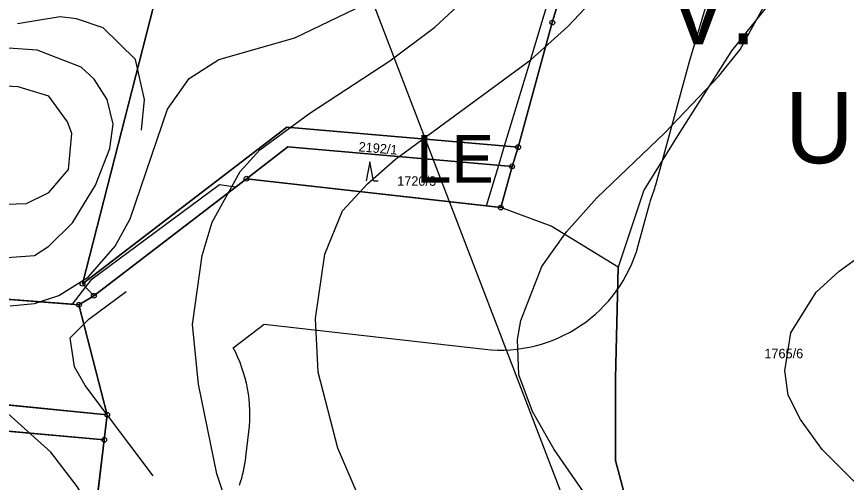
# Model space of a CAD drawing. Extents: x -706130 to -698555, y -971544 to -967260.
# Drawn here: x -703788.9 to -703614.4, y -970856.1 to -970758.1 of the extents above; entities that cross this region are included whole.
import ezdxf

# ---------------------------------------------------------------- set-up
doc = ezdxf.new("R2010")
doc.units = 0
for name, color, linetype in [('Archeologická naleziště S', 7, 'Continuous'), ('BPEJ hranice S', 7, 'Continuous'), ('BPEJ kód', 7, 'Continuous'), ('KN_Hranice_parcel', 7, 'Continuous'), ('KN_Parcelni cisla', 7, 'Continuous'), ('KN_Polygon parcely', 7, 'Continuous'), ('KN_Popisy_pomistni nazvy', 7, 'Continuous'), ('KN_POZEMKY_10_LESNI POZEMEK', 7, 'Continuous'), ('KN_POZEMKY_14_OSTATNI PLOCHA', 7, 'Continuous'), ('KN_POZEMKY_2_ORNA PUDA', 7, 'Continuous'), ('KN_POZEMKY_7_TTP', 7, 'Continuous'), ('KN_VYUZITI_17_ostatni plocha_ostatni komunikace', 7, 'Continuous'), ('KN_Značky bodu BP', 7, 'Continuous'), ('KN_Značky kultur', 7, 'Continuous'), ('OP lesa 30 m', 7, 'Continuous'), ('Plochy lesní všeobecné S', 7, 'Continuous'), ('Plochy smíšené nezastavěného území všeobecné S', 7, 'Continuous'), ('Plochy zemědělské všeobecné CELEK S', 7, 'Continuous'), ('Regulační bloky v krajině S', 7, 'Continuous'), ('Regulační kódy v krajině S', 7, 'Continuous'), ('VÝŠKOPIS_vrstevnice doplňková', 7, 'Continuous'), ('VÝŠKOPIS_vrstevnice hlavní', 7, 'Continuous'), ('VÝŠKOPIS_vrstevnice zesílená', 7, 'Continuous')]:
    doc.layers.add(name, color=color, linetype=linetype)

msp = doc.modelspace()

# ---------------------------------------------------------------- linework, layer by layer
at = {"layer": 'Archeologická naleziště S'}
msp.add_lwpolyline([(-703408.7, -970993.88), (-703586.12, -970875.94), (-703659.44, -970897.19), (-703878.38, -970326.38), (-703591.19, -970210.38), (-703362.81, -970550.62), (-703335.44, -970886.44), (-703375.42, -970994.48)], dxfattribs=at)
at = {"layer": 'BPEJ hranice S'}
msp.add_lwpolyline([(-703610.36, -970734.42), (-703626.08, -970749.6), (-703638.54, -970765.32), (-703649.93, -970783.22), (-703656.97, -970794.61), (-703662.39, -970810.87), (-703676.48, -970802.2), (-703687.07, -970798.29), (-703690.06, -970797.95), (-703687.48, -970789.38), (-703686.27, -970785.33), (-703681.41, -970769.19), (-703664.61, -970713.33), (-703662.71, -970713.82), (-703661.78, -970710.7), (-703652.29, -970713.13), (-703624.44, -970674.38), (-703619.55, -970649.23), (-703617.35, -970637.9), (-703616.01, -970640.13), (-703611.44, -970647.66), (-703602.77, -970671.52), (-703599.52, -970695.92), (-703607.47, -970724.18)], close=True, dxfattribs=at)
for points in [[(-703610.36, -970734.42), (-703626.08, -970749.6), (-703638.54, -970765.32), (-703649.93, -970783.22), (-703656.97, -970794.61), (-703662.39, -970810.87), (-703662.93, -970834.19), (-703662.93, -970851.54), (-703658.06, -970869.98), (-703652.64, -970879.74), (-703649.38, -970890.04), (-703645.59, -970903.05), (-703647.22, -970913.36), (-703652.5, -970929.64), (-703652.72, -970930.32), (-703653.01, -970930.44), (-703655.3, -970934.05), (-703638.24, -970924.1)], [(-703658.06, -970869.98), (-703662.93, -970851.54), (-703662.93, -970834.19), (-703662.39, -970810.87), (-703676.48, -970802.2), (-703687.07, -970798.29), (-703690.06, -970797.95), (-703740.55, -970792.22), (-703742.86, -970794), (-703746.18, -970793.51), (-703773.29, -970813.55), (-703774.39, -970815), (-703777.16, -970818.64), (-703839.77, -970813.83)]]:
    msp.add_lwpolyline(points, dxfattribs=at)
at = {"layer": 'KN_Hranice_parcel'}
for p, q in [((-703775.02, -970814.32), (-703760.08, -970755.96)), ((-703683.41, -970785.58), (-703684.68, -970789.62)), ((-703740.55, -970792.22), (-703772.64, -970816.86)), ((-703772.64, -970816.86), (-703775.02, -970814.32)), ((-703775.76, -970818.75), (-703772.64, -970816.86)), ((-703769.81, -970841.91), (-703775.76, -970818.75)), ((-703770.44, -970847.18), (-703769.81, -970841.91)), ((-703773.25, -970870.48), (-703770.44, -970847.18))]:
    msp.add_line(p, q, dxfattribs=at)
for points in [[(-703661.78, -970710.7), (-703676.23, -970759.35), (-703683.41, -970785.58)], [(-703775.76, -970818.75), (-703839.77, -970813.83), (-703846.84, -970815.09), (-703851.88, -970814.56), (-703856.96, -970809.13), (-703881.57, -970766.76)], [(-703683.41, -970785.58), (-703732.08, -970781.35), (-703775.02, -970814.32)], [(-703684.68, -970789.62), (-703731.82, -970785.52), (-703740.55, -970792.22)], [(-703740.55, -970792.22), (-703687.07, -970798.29), (-703684.68, -970789.62)], [(-703989.92, -970846.6), (-703937.75, -970850.36), (-703894.43, -970839.26), (-703857.78, -970833.24), (-703855.98, -970839.32), (-703832.43, -970835.75), (-703769.81, -970841.91)], [(-703989.92, -970846.6), (-703989.49, -970852.8), (-703936.63, -970856.11), (-703906.07, -970852.91), (-703831.71, -970841.68), (-703770.44, -970847.18)]]:
    msp.add_lwpolyline(points, dxfattribs=at)
at = {"layer": 'KN_Polygon parcely'}
for points in [[(-703708.42, -970692.67), (-703760.08, -970755.96), (-703775.02, -970814.32), (-703732.08, -970781.35), (-703683.41, -970785.58), (-703676.23, -970759.35), (-703661.78, -970710.7), (-703694.43, -970698.08)], [(-703775.02, -970814.32), (-703760.08, -970755.96), (-703788.35, -970753.55), (-703835.64, -970758.02), (-703881.57, -970766.76), (-703856.96, -970809.13), (-703851.88, -970814.56), (-703846.84, -970815.09), (-703839.77, -970813.83), (-703775.76, -970818.75), (-703772.64, -970816.86)], [(-703855.98, -970839.32), (-703832.43, -970835.75), (-703769.81, -970841.91), (-703775.76, -970818.75), (-703839.77, -970813.83), (-703846.84, -970815.09), (-703851.88, -970814.56), (-703856.96, -970809.13), (-703881.57, -970766.76), (-703927.53, -970774.91), (-703944.45, -970781.48), (-703945.45, -970778.27), (-703954.28, -970779.83), (-703961.3, -970781.02), (-703994.19, -970784.24), (-703989.92, -970846.6), (-703937.75, -970850.36), (-703894.43, -970839.26), (-703857.78, -970833.24)], [(-703732.08, -970781.35), (-703775.02, -970814.32), (-703772.64, -970816.86), (-703740.55, -970792.22), (-703731.82, -970785.52), (-703684.68, -970789.62), (-703683.41, -970785.58)], [(-703684.68, -970789.62), (-703731.82, -970785.52), (-703740.55, -970792.22), (-703687.07, -970798.29)], [(-703936.63, -970856.11), (-703906.07, -970852.91), (-703831.71, -970841.68), (-703770.44, -970847.18), (-703769.81, -970841.91), (-703832.43, -970835.75), (-703855.98, -970839.32), (-703857.78, -970833.24), (-703894.43, -970839.26), (-703937.75, -970850.36), (-703989.92, -970846.6), (-703989.49, -970852.8)]]:
    msp.add_lwpolyline(points, close=True, dxfattribs=at)
for points in [[(-703589.18, -970728.12), (-703614.93, -970722.57), (-703651.67, -970713.29), (-703661.78, -970710.7), (-703676.23, -970759.35), (-703683.41, -970785.58), (-703684.68, -970789.62), (-703687.07, -970798.29), (-703740.55, -970792.22), (-703772.64, -970816.86), (-703775.76, -970818.75), (-703769.81, -970841.91), (-703770.44, -970847.18), (-703773.25, -970870.48), (-703690.2, -970934.86), (-703665.69, -970942.39), (-703657.66, -970935.42), (-703638.24, -970924.1), (-703636.35, -970922.15), (-703634.1, -970919.81), (-703614.35, -970903.64)], [(-704100.66, -971058.2), (-704059.31, -971011.16), (-704005.5, -970949.94), (-703866.81, -970867.73), (-703847.86, -970860.46), (-703830.98, -970859.35), (-703773.25, -970870.48), (-703770.44, -970847.18), (-703831.71, -970841.68), (-703906.07, -970852.91), (-703936.63, -970856.11), (-703989.49, -970852.8), (-703989.92, -970846.6), (-703994.19, -970784.24), (-704032.18, -970780.18), (-704105.96, -970769.41)]]:
    msp.add_lwpolyline(points, dxfattribs=at)
at = {"layer": 'KN_POZEMKY_10_LESNI POZEMEK'}
for p, q in [((-703661.78, -970710.7), (-703676.23, -970759.35)), ((-703760.08, -970755.96), (-703775.02, -970814.32)), ((-703775.02, -970814.32), (-703760.08, -970755.96)), ((-703676.23, -970759.35), (-703683.41, -970785.58)), ((-703732.08, -970781.35), (-703775.02, -970814.32)), ((-703683.41, -970785.58), (-703732.08, -970781.35)), ((-703740.55, -970792.22), (-703731.82, -970785.52)), ((-703731.82, -970785.52), (-703684.68, -970789.62)), ((-703684.68, -970789.62), (-703687.07, -970798.29)), ((-703687.07, -970798.29), (-703740.55, -970792.22)), ((-703775.76, -970818.75), (-703839.77, -970813.83)), ((-703775.02, -970814.32), (-703772.64, -970816.86)), ((-703772.64, -970816.86), (-703775.76, -970818.75)), ((-703832.43, -970835.75), (-703769.81, -970841.91)), ((-703770.44, -970847.18), (-703831.71, -970841.68)), ((-703769.81, -970841.91), (-703770.44, -970847.18))]:
    msp.add_line(p, q, dxfattribs=at)
at = {"layer": 'KN_POZEMKY_14_OSTATNI PLOCHA'}
for p, q in [((-703775.02, -970814.32), (-703732.08, -970781.35)), ((-703732.08, -970781.35), (-703683.41, -970785.58)), ((-703731.82, -970785.52), (-703740.55, -970792.22)), ((-703684.68, -970789.62), (-703731.82, -970785.52)), ((-703683.41, -970785.58), (-703684.68, -970789.62)), ((-703740.55, -970792.22), (-703772.64, -970816.86)), ((-703772.64, -970816.86), (-703775.02, -970814.32))]:
    msp.add_line(p, q, dxfattribs=at)
at = {"layer": 'KN_POZEMKY_2_ORNA PUDA'}
for p, q in [((-703676.23, -970759.35), (-703661.78, -970710.7)), ((-703683.41, -970785.58), (-703676.23, -970759.35)), ((-703684.68, -970789.62), (-703683.41, -970785.58)), ((-703687.07, -970798.29), (-703684.68, -970789.62)), ((-703772.64, -970816.86), (-703740.55, -970792.22)), ((-703740.55, -970792.22), (-703687.07, -970798.29)), ((-703775.76, -970818.75), (-703772.64, -970816.86)), ((-703769.81, -970841.91), (-703775.76, -970818.75)), ((-703831.71, -970841.68), (-703770.44, -970847.18)), ((-703770.44, -970847.18), (-703769.81, -970841.91)), ((-703773.25, -970870.48), (-703770.44, -970847.18)), ((-703770.44, -970847.18), (-703773.25, -970870.48))]:
    msp.add_line(p, q, dxfattribs=at)
at = {"layer": 'KN_POZEMKY_7_TTP'}
for p, q in [((-703839.77, -970813.83), (-703775.76, -970818.75)), ((-703775.76, -970818.75), (-703769.81, -970841.91)), ((-703769.81, -970841.91), (-703832.43, -970835.75))]:
    msp.add_line(p, q, dxfattribs=at)
at = {"layer": 'KN_VYUZITI_17_ostatni plocha_ostatni komunikace'}
for p, q in [((-703775.02, -970814.32), (-703732.08, -970781.35)), ((-703732.08, -970781.35), (-703683.41, -970785.58)), ((-703731.82, -970785.52), (-703740.55, -970792.22)), ((-703684.68, -970789.62), (-703731.82, -970785.52)), ((-703683.41, -970785.58), (-703684.68, -970789.62)), ((-703740.55, -970792.22), (-703772.64, -970816.86)), ((-703772.64, -970816.86), (-703775.02, -970814.32))]:
    msp.add_line(p, q, dxfattribs=at)
at = {"layer": 'KN_Značky bodu BP'}
for centre, radius in [((-703676.23, -970759.35), 0.5), ((-703676.23, -970759.35), 0.0303), ((-703683.41, -970785.58), 0.5), ((-703683.41, -970785.58), 0.0303), ((-703684.68, -970789.62), 0.5), ((-703684.68, -970789.62), 0.0303), ((-703740.55, -970792.22), 0.5), ((-703740.55, -970792.22), 0.0303), ((-703687.07, -970798.29), 0.5), ((-703687.07, -970798.29), 0.0303), ((-703775.02, -970814.32), 0.5), ((-703775.02, -970814.32), 0.0303), ((-703772.64, -970816.86), 0.5), ((-703772.64, -970816.86), 0.0303), ((-703775.76, -970818.75), 0.5), ((-703775.76, -970818.75), 0.0303), ((-703769.81, -970841.91), 0.5), ((-703769.81, -970841.91), 0.0303), ((-703770.44, -970847.18), 0.5), ((-703770.44, -970847.18), 0.0303)]:
    msp.add_circle(centre, radius, dxfattribs=at)
at = {"layer": 'KN_Značky kultur'}
for p, q in [((-703714.61, -970788.69), (-703715.36, -970792.69)), ((-703713.86, -970792.69), (-703714.61, -970788.69)), ((-703713.86, -970792.69), (-703712.86, -970792.69))]:
    msp.add_line(p, q, dxfattribs=at)
at = {"layer": 'OP lesa 30 m'}
for p, q in [((-703658.15, -970806.26), (-703655.76, -970797.59)), ((-703740.65, -970850.74), (-703740.02, -970845.47))]:
    msp.add_line(p, q, dxfattribs=at)
for points in [[(-703654.47, -970793.5), (-703647.38, -970767.58), (-703639.38, -970740.66)], [(-703743.33, -970827.81), (-703736.85, -970822.83), (-703690.45, -970828.1)]]:
    msp.add_lwpolyline(points, dxfattribs=at)
for centre, start, end in [((-703683.41, -970785.58), 338.5017, 344.6913), ((-703684.68, -970789.62), 344.5884, 346.5965), ((-703687.07, -970798.29), 263.5246, 344.5884), ((-703769.81, -970841.91), 353.183, 28.0327), ((-703770.44, -970847.18), 341.4122, 353.183)]:
    msp.add_arc(centre, 30, start, end, dxfattribs=at)
at = {"layer": 'Plochy lesní všeobecné S'}
for p, q in [((-703676.23, -970759.35), (-703661.78, -970710.7)), ((-703683.41, -970785.58), (-703676.23, -970759.35)), ((-703775.02, -970814.32), (-703732.08, -970781.35)), ((-703732.08, -970781.35), (-703683.41, -970785.58)), ((-703731.82, -970785.52), (-703740.55, -970792.22)), ((-703684.68, -970789.62), (-703731.82, -970785.52)), ((-703687.07, -970798.29), (-703684.68, -970789.62)), ((-703740.55, -970792.22), (-703687.07, -970798.29)), ((-703839.77, -970813.83), (-703775.76, -970818.75)), ((-703772.64, -970816.86), (-703775.02, -970814.32)), ((-703775.76, -970818.75), (-703772.64, -970816.86))]:
    msp.add_line(p, q, dxfattribs=at)
at = {"layer": 'Plochy smíšené nezastavěného území všeobecné S'}
for p, q in [((-703740.55, -970792.22), (-703731.82, -970785.52)), ((-703731.82, -970785.52), (-703684.68, -970789.62)), ((-703684.68, -970789.62), (-703683.41, -970785.58)), ((-703772.64, -970816.86), (-703740.55, -970792.22)), ((-703775.02, -970814.32), (-703772.64, -970816.86))]:
    msp.add_line(p, q, dxfattribs=at)
msp.add_lwpolyline([(-703683.41, -970785.58), (-703732.08, -970781.35), (-703775.02, -970814.32)], dxfattribs=at)
at = {"layer": 'Plochy zemědělské všeobecné CELEK S'}
for p, q in [((-703661.78, -970710.7), (-703676.23, -970759.35)), ((-703676.23, -970759.35), (-703683.41, -970785.58)), ((-703683.41, -970785.58), (-703684.68, -970789.62)), ((-703684.68, -970789.62), (-703687.07, -970798.29)), ((-703740.55, -970792.22), (-703772.64, -970816.86)), ((-703687.07, -970798.29), (-703740.55, -970792.22)), ((-703775.76, -970818.75), (-703839.77, -970813.83)), ((-703772.64, -970816.86), (-703775.76, -970818.75))]:
    msp.add_line(p, q, dxfattribs=at)
at = {"layer": 'Regulační bloky v krajině S'}
for p, q in [((-703676.23, -970759.35), (-703661.78, -970710.7)), ((-703661.78, -970710.7), (-703676.23, -970759.35)), ((-703683.41, -970785.58), (-703676.23, -970759.35)), ((-703676.23, -970759.35), (-703683.41, -970785.58)), ((-703775.02, -970814.32), (-703732.08, -970781.35)), ((-703732.08, -970781.35), (-703683.41, -970785.58)), ((-703731.82, -970785.52), (-703740.55, -970792.22)), ((-703740.55, -970792.22), (-703731.82, -970785.52)), ((-703684.68, -970789.62), (-703731.82, -970785.52)), ((-703731.82, -970785.52), (-703684.68, -970789.62)), ((-703684.68, -970789.62), (-703683.41, -970785.58)), ((-703683.41, -970785.58), (-703684.68, -970789.62)), ((-703687.07, -970798.29), (-703684.68, -970789.62)), ((-703684.68, -970789.62), (-703687.07, -970798.29)), ((-703772.64, -970816.86), (-703740.55, -970792.22)), ((-703740.55, -970792.22), (-703772.64, -970816.86)), ((-703740.55, -970792.22), (-703687.07, -970798.29)), ((-703687.07, -970798.29), (-703740.55, -970792.22)), ((-703839.77, -970813.83), (-703775.76, -970818.75)), ((-703775.76, -970818.75), (-703839.77, -970813.83)), ((-703772.64, -970816.86), (-703775.02, -970814.32)), ((-703775.02, -970814.32), (-703772.64, -970816.86)), ((-703775.76, -970818.75), (-703772.64, -970816.86)), ((-703772.64, -970816.86), (-703775.76, -970818.75))]:
    msp.add_line(p, q, dxfattribs=at)
msp.add_lwpolyline([(-703683.41, -970785.58), (-703732.08, -970781.35), (-703775.02, -970814.32)], dxfattribs=at)
at = {"layer": 'VÝŠKOPIS_vrstevnice doplňková'}
for points in [[(-703762.58, -970781.99), (-703762.01, -970775.58), (-703763.87, -970767.16), (-703770.69, -970760.44), (-703776.28, -970758.6), (-703779.71, -970758.17), (-703788.69, -970759.6)], [(-703778.14, -970780.28), (-703782.13, -970774.86), (-703788.55, -970772.86), (-703792.57, -970772.7), (-703798.38, -970776.01), (-703801.39, -970780.57), (-703801.68, -970783.28), (-703799.68, -970791.98), (-703795.97, -970796.41), (-703791.12, -970797.55), (-703786.81, -970797.44), (-703782.1, -970795.13), (-703777.99, -970790.27), (-703777.28, -970782.71), (-703778.14, -970780.28)], [(-703760.16, -970854.76), (-703774.43, -970835.78), (-703776.71, -970831.79), (-703777.61, -970825.72), (-703773.71, -970821.8), (-703765.86, -970815.95)]]:
    msp.add_lwpolyline(points, dxfattribs=at)
at = {"layer": 'VÝŠKOPIS_vrstevnice hlavní'}
for points in [[(-703667.14, -970861.75), (-703675.84, -970849.19), (-703680.41, -970841.2), (-703683.26, -970833.5), (-703683.54, -970826.08), (-703682.83, -970822.09), (-703678.41, -970810.67), (-703673.27, -970803.4), (-703666.85, -970796.26), (-703652.59, -970782.57), (-703641.31, -970770.72), (-703636.75, -970765.02), (-703630.61, -970753.89), (-703627.33, -970743.9), (-703624.34, -970725.93), (-703624.76, -970705.95), (-703628.05, -970672), (-703630.19, -970658.01), (-703633.61, -970646.32), (-703638.03, -970636.33), (-703645.02, -970626.48), (-703651.87, -970621.06)], [(-703668.39, -970943.62), (-703670.42, -970936.51), (-703677.27, -970921.1), (-703702.38, -970884.86), (-703709.8, -970872.88), (-703717.07, -970858.9), (-703721.35, -970848.91), (-703725.49, -970832.93), (-703726.06, -970821.66), (-703724.06, -970808.1), (-703720.35, -970798.97), (-703715.07, -970793.27), (-703709.23, -970788.13), (-703680.69, -970767.16), (-703672.99, -970760.17), (-703664.43, -970751.04), (-703658.15, -970741.05), (-703653.58, -970731.06), (-703650.87, -970723.07), (-703646.02, -970703.1), (-703644.31, -970689.12), (-703645.45, -970677.99), (-703649.02, -970664.01)], [(-703790.26, -970818.95), (-703785.13, -970818.52), (-703779.99, -970816.81), (-703773.86, -970812.95), (-703768.15, -970806.39), (-703765.01, -970800.69), (-703757.16, -970777.57), (-703752.6, -970771.15), (-703746.32, -970767.16), (-703730.34, -970762.59), (-703710.37, -970752.89)], [(-703772.57, -970771.29), (-703775.28, -970768.73), (-703784.56, -970765.16), (-703790.55, -970764.73), (-703794.54, -970765.45), (-703802.53, -970769.44), (-703807.67, -970774.43), (-703809.52, -970778.57), (-703810.52, -970787.56), (-703807.24, -970796.69), (-703802.1, -970804.39), (-703795.6, -970807.89), (-703790.83, -970808.82), (-703785.13, -970808.39), (-703782.13, -970806.39), (-703777.14, -970801.54), (-703772.29, -970793.55), (-703769.29, -970785.85), (-703768.58, -970780.71), (-703769.86, -970775.58), (-703772.57, -970771.29)], [(-703599.37, -970869.45), (-703619.49, -970849.19), (-703624.05, -970842.92), (-703626.62, -970837.78), (-703627.33, -970832.64), (-703626.05, -970824.65), (-703620.77, -970816.09), (-703615.92, -970811.67), (-703606.22, -970804.68)], [(-703732.98, -970951.27), (-703733.19, -970949.35), (-703735.19, -970939.36), (-703738.9, -970926.52), (-703745.04, -970910.83), (-703755.74, -970890.85), (-703776.14, -970857.04), (-703781.7, -970849.76), (-703793.54, -970839.21), (-703802.82, -970833.64), (-703814.8, -970829.65), (-703823.36, -970828.22), (-703843.91, -970828.93), (-703854.18, -970830.93), (-703869.59, -970836.78), (-703890.13, -970848.19)]]:
    msp.add_lwpolyline(points, dxfattribs=at)
at = {"layer": 'VÝŠKOPIS_vrstevnice zesílená'}
msp.add_lwpolyline([(-703740.47, -970873.16), (-703746.75, -970854.33), (-703750.6, -970835.5), (-703751.88, -970822.94), (-703749.89, -970808.39), (-703747.75, -970801.4), (-703741.9, -970790.7), (-703737.76, -970786.13), (-703727.2, -970778.43), (-703710.37, -970767.44), (-703700.95, -970760.31), (-703692.39, -970752.32)], dxfattribs=at)

# ---------------------------------------------------------------- texts
at = {"layer": 'BPEJ kód'}
msp.add_text('V.', height=15, dxfattribs=at).set_placement((-703652.24, -970763.93))
at = {"layer": 'KN_Parcelni cisla'}
msp.add_text('2192/1', height=2, rotation=355, dxfattribs=at).set_placement((-703717.03, -970786.45))
for s, p in [('1720/3', (-703708.85, -970793.71)), ('1765/6', (-703631.65, -970830.02))]:
    msp.add_text(s, height=2, dxfattribs=at).set_placement(p)
at = {"layer": 'KN_Popisy_pomistni nazvy'}
msp.add_text('U Nové Starosti', height=15, dxfattribs=at).set_placement((-703627.32, -970788.97))
at = {"layer": 'Regulační kódy v krajině S'}
msp.add_text('LE', height=10, dxfattribs=at).set_placement((-703704.88, -970793.02))

doc.saveas('drawing.dxf')
